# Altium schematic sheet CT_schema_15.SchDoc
size 388 x 385 mm
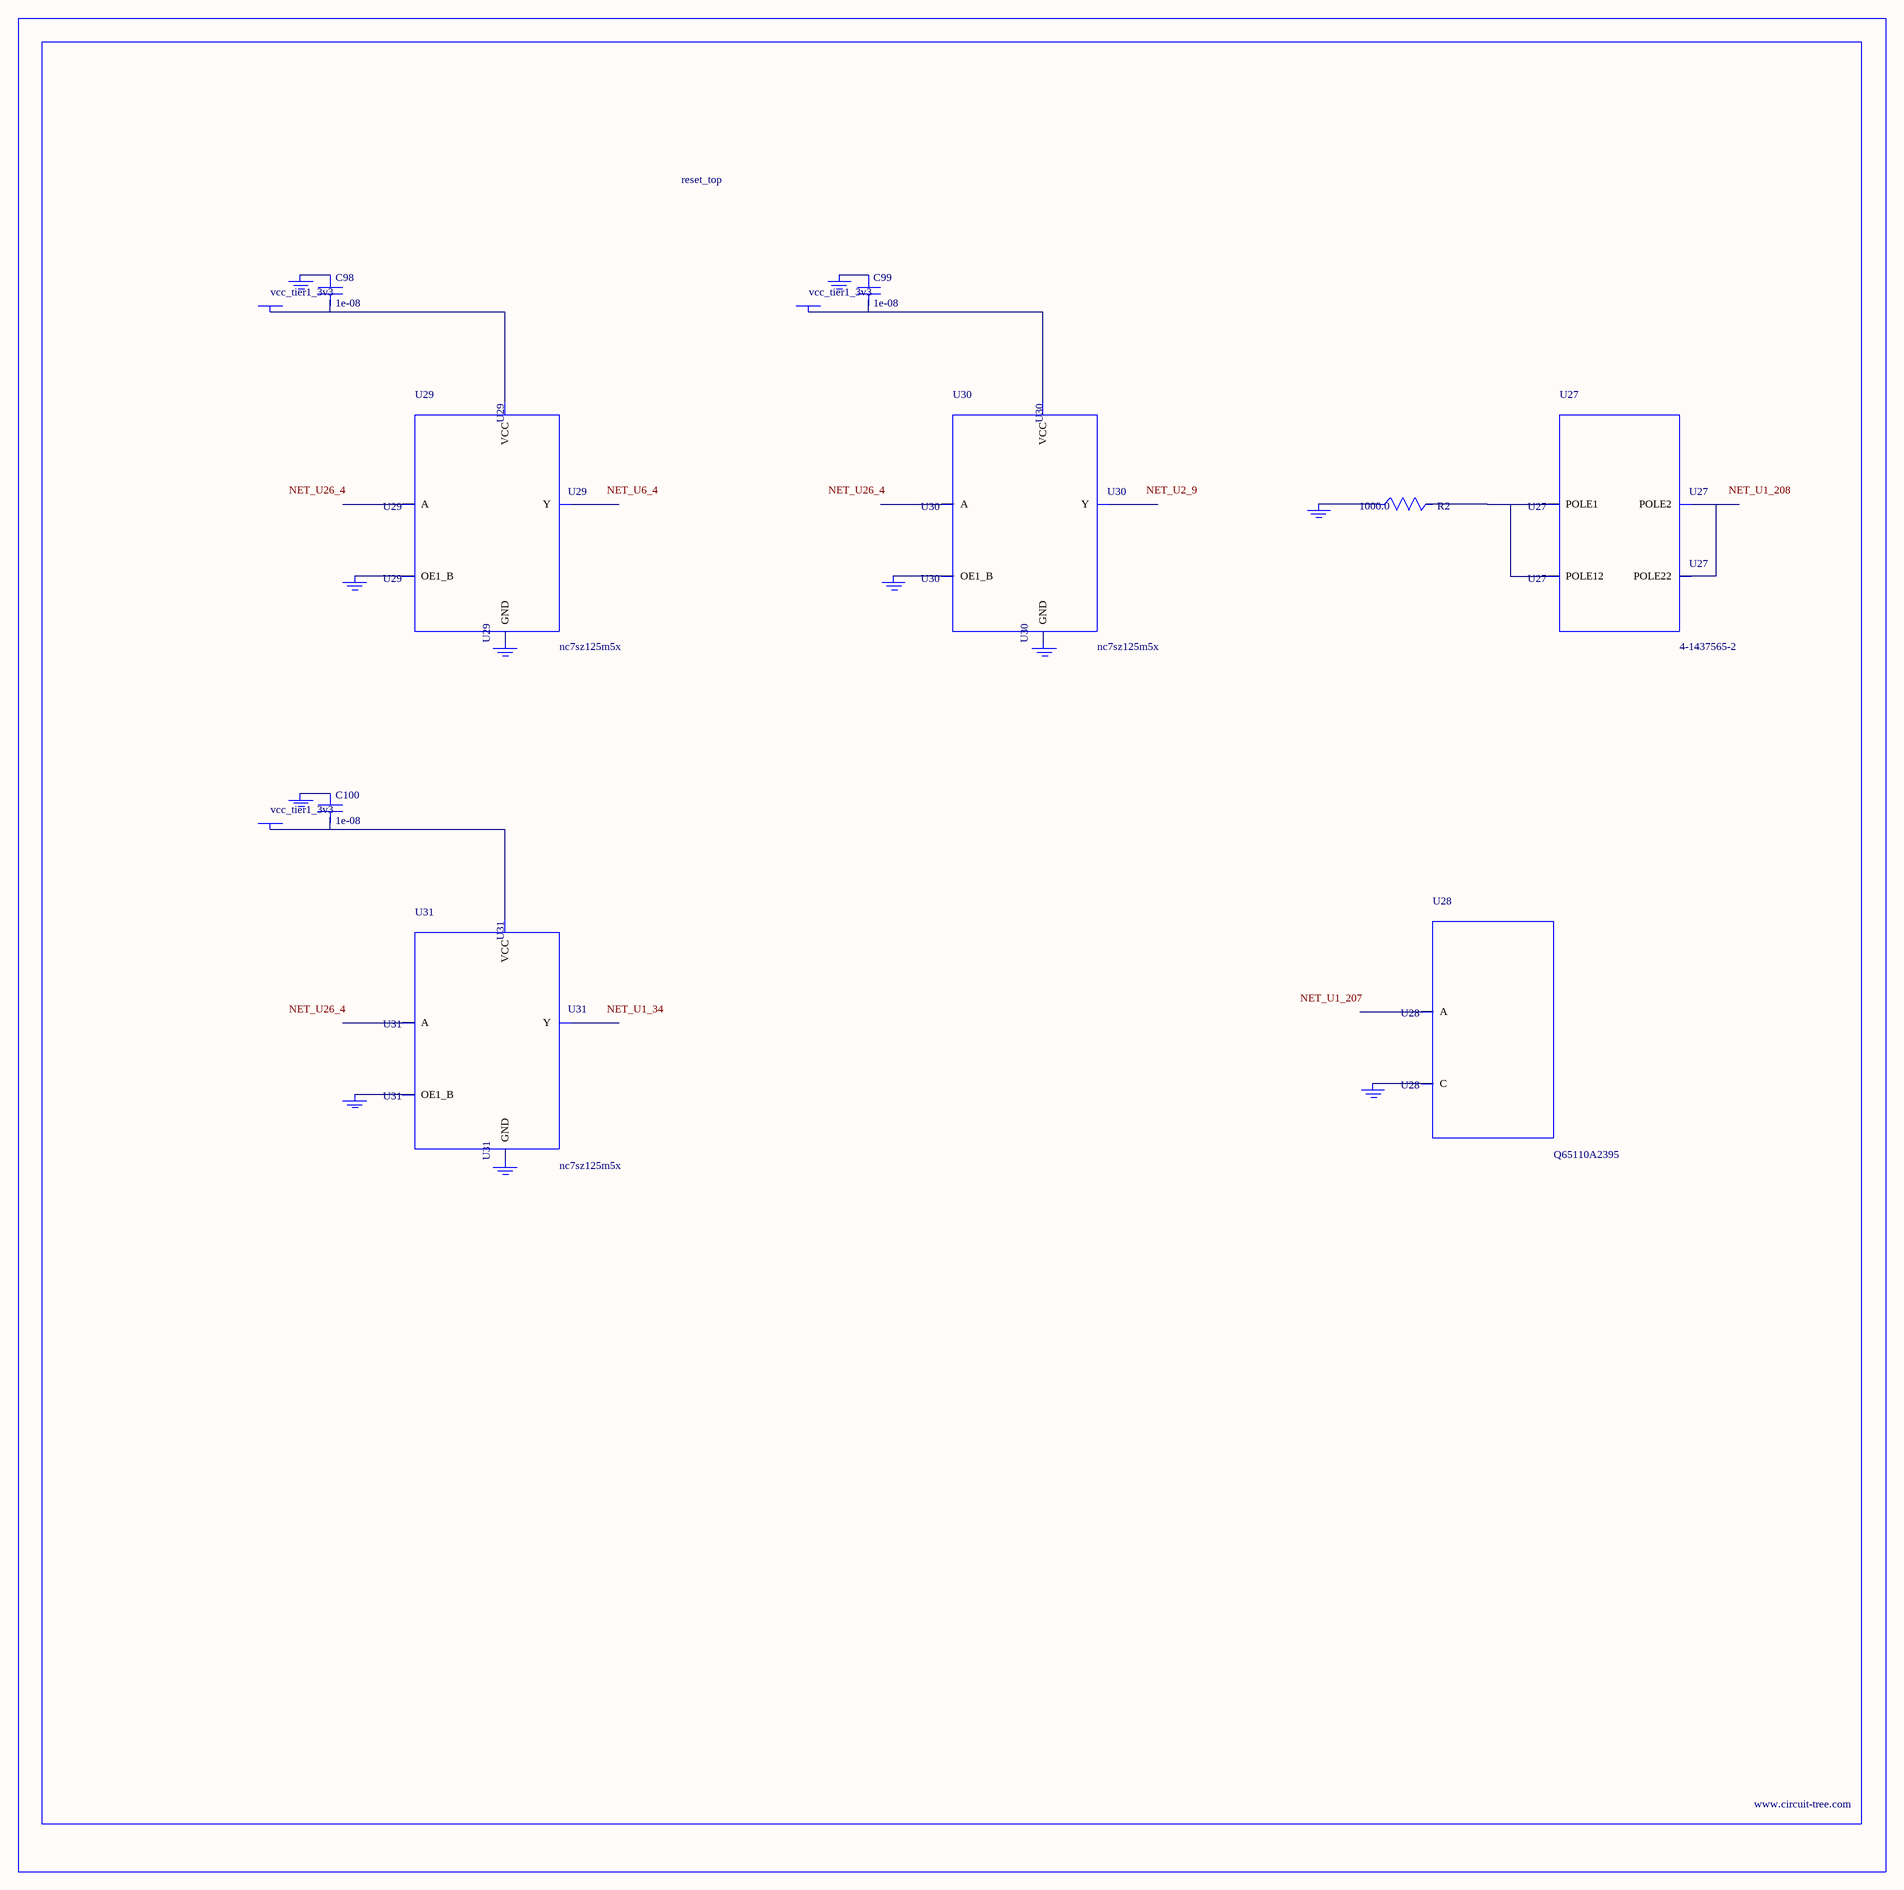
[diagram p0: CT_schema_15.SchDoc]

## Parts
BORDER14  (no value)
C98  1e-08  [C0402]
C99  1e-08  [C0402]
C100  1e-08  [C0402]
GND_INSTANCE_14_0  (no value)
GND_INSTANCE_14_1  (no value)
GND_INSTANCE_14_2  (no value)
GND_INSTANCE_14_3  (no value)
GND_INSTANCE_14_4  (no value)
GND_INSTANCE_14_5  (no value)
GND_INSTANCE_14_6  (no value)
GND_INSTANCE_14_7  (no value)
GND_INSTANCE_14_8  (no value)
GND_INSTANCE_14_9  (no value)
GND_INSTANCE_14_10  (no value)
POWER_INSTANCE_14_0  vcc_tier1_3v3
POWER_INSTANCE_14_1  vcc_tier1_3v3
POWER_INSTANCE_14_2  vcc_tier1_3v3
R2  1000.0  [R0603]
U27  4-1437565-2  [SW_4-1437565-2]
U28  Q65110A2395  [LGM67K-G1J2-24-Z]
U29  nc7sz125m5x  [NC7SZ125M5X]
U30  nc7sz125m5x  [NC7SZ125M5X]
U31  nc7sz125m5x  [NC7SZ125M5X]

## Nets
NetC98_1: C98.1 GND_INSTANCE_14_2.0(GND)
NetC98_2: C98.2 POWER_INSTANCE_14_0.0(PWR) U29.5(VCC)
NetC99_1: C99.1 GND_INSTANCE_14_5.0(GND)
NetC99_2: C99.2 POWER_INSTANCE_14_1.0(PWR) U30.5(VCC)
NetC100_1: C100.1 GND_INSTANCE_14_8.0(GND)
NetC100_2: C100.2 POWER_INSTANCE_14_2.0(PWR) U31.5(VCC)
NetGND_INSTANCE_14_0_0: GND_INSTANCE_14_0.0(GND) R2.1
NetGND_INSTANCE_14_1_0: GND_INSTANCE_14_1.0(GND) U28.C
NetGND_INSTANCE_14_3_0: GND_INSTANCE_14_3.0(GND) U29.1(OE1_B)
NetGND_INSTANCE_14_4_0: GND_INSTANCE_14_4.0(GND) U29.3(GND)
NetGND_INSTANCE_14_6_0: GND_INSTANCE_14_6.0(GND) U30.1(OE1_B)
NetGND_INSTANCE_14_7_0: GND_INSTANCE_14_7.0(GND) U30.3(GND)
NetGND_INSTANCE_14_9_0: GND_INSTANCE_14_9.0(GND) U31.1(OE1_B)
NetGND_INSTANCE_14_10_0: GND_INSTANCE_14_10.0(GND) U31.3(GND)
NetR2_2: R2.2 U27.1(POLE1) U27.2(POLE12)
NetU27_3: U27.3(POLE2) U27.4(POLE22)

Not connected (* = marked no-connect by the designer): U28 A; U29 2(A) 4(Y); U30 2(A) 4(Y); U31 2(A) 4(Y)

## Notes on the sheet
- Labels drawn without touching a wire or pin: NET_U1_34, NET_U1_207, NET_U1_208, NET_U2_9, NET_U6_4, NET_U26_4

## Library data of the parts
BORDER14 = BORDER_PAGE14
C98-C100 = C0402C103K3RAC
GND_INSTANCE_14_0-GND_INSTANCE_14_10 = GND
POWER_INSTANCE_14_0-POWER_INSTANCE_14_2 = PWR
R2 = RC0603JR-071KL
